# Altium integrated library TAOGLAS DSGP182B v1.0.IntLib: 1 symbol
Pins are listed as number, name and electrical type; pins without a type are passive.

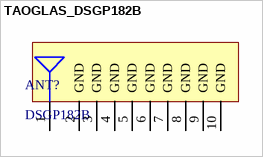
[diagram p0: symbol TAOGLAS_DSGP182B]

## TAOGLAS_DSGP182B
designator ANT?, comment DSGP182B
GPS L1 / GALILEO E1 1575.42MHz 18*18*2mm Ceramic Patch SMD Antenna; ComponentLibStatus: Created; MFG: Taoglas; Temp_High: +85C; Temp_Low: -40C
footprint TAOGLAS_DSGP182B (GPS L1 / GALILEO E1 1575.42MHz 18*18*2mm Ceramic Patch SMD Antenna)
pins: 1 RF FEED, 2 GND, 3 GND, 4 GND, 5 GND, 6 GND, 7 GND, 8 GND, 9 GND, 10 GND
